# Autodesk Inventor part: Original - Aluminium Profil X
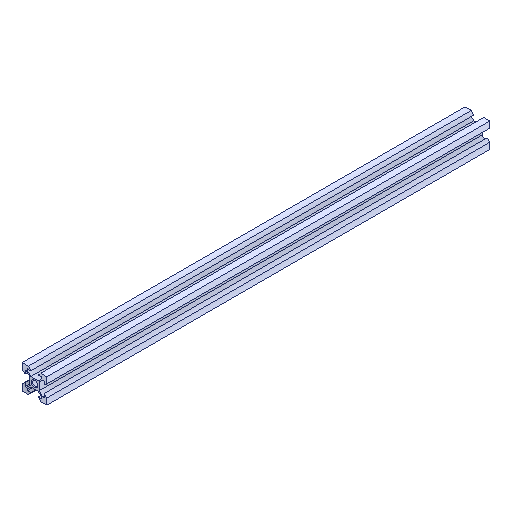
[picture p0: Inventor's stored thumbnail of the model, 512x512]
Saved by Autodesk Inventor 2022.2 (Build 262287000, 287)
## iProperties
Created: 2024-09
Part Number: Original - Aluminium Profil X
Material: Generico
Document SubType Name: Modeling
Designer: 18907419
Density: 1 g/cm^3
Appearance: Default
Author: 18907419
Revision Number: ANY
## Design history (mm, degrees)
feature "Fase1"
node "Solido1"
